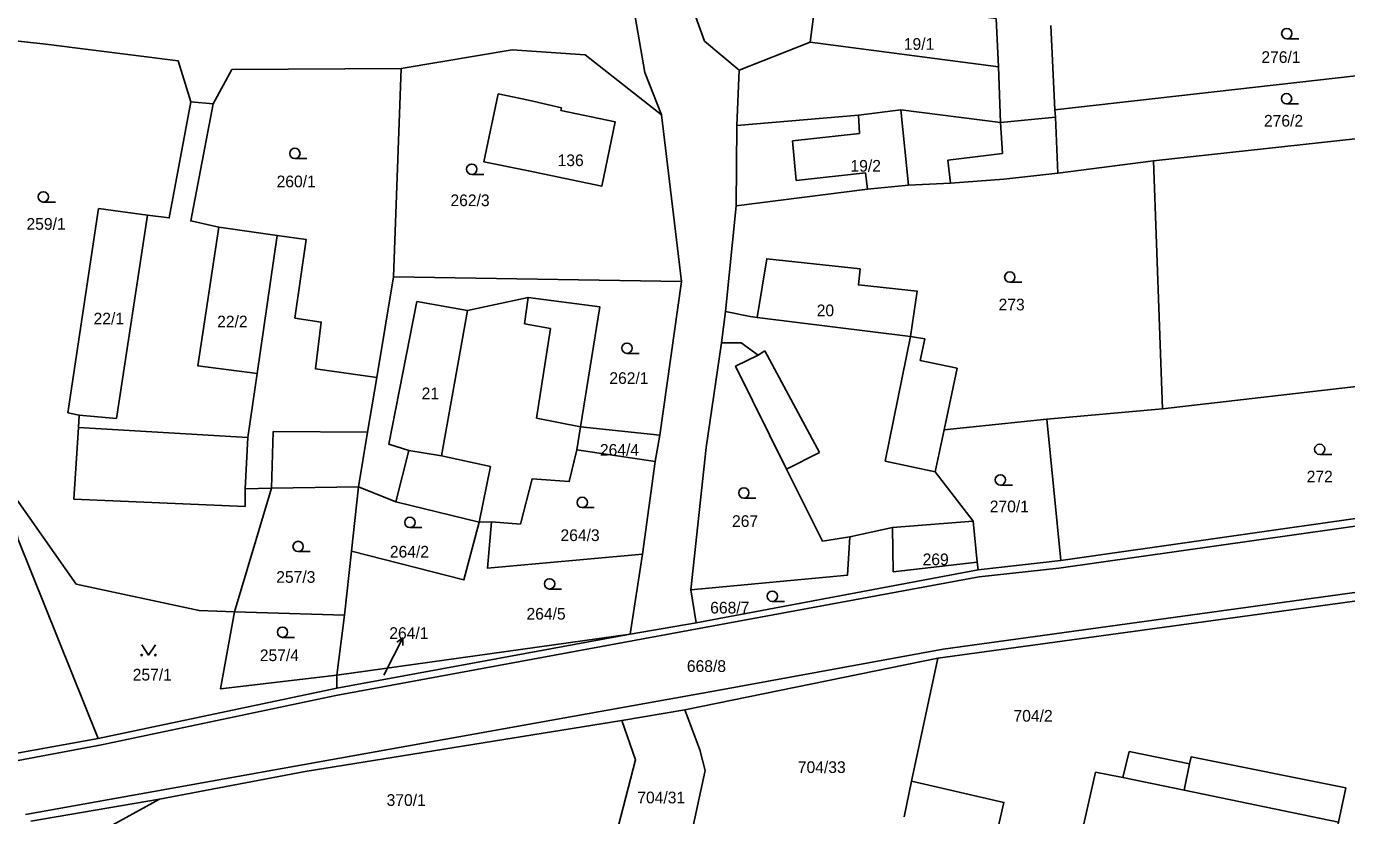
# Model space of a CAD drawing. Extents: x -747333 to -743907, y -1134120 to -1130051.
# Drawn here: x -746332 to -746140.1, y -1132327 to -1132212.3 of the extents above; entities that cross this region are included whole.
import ezdxf

# ---------------------------------------------------------------- set-up
doc = ezdxf.new("R2010")
doc.units = 0
for name, color, linetype in [('Hranice parcel', 7, 'Continuous'), ('Parcelní čísla', 7, 'Continuous'), ('Pop  PČ popisy', 7, 'Continuous'), ('Vnitřní kresba', 7, 'Continuous'), ('Značky kultur', 7, 'Continuous')]:
    doc.layers.add(name, color=color, linetype=linetype)

msp = doc.modelspace()

# ---------------------------------------------------------------- linework, layer by layer
at = {"layer": 'Hranice parcel'}
for p, q in [((-746182.52, -1132224.41), (-746183.12, -1132212.16)), ((-746182.52, -1132224.41), (-746109, -1132216.08)), ((-746278.68, -1132248.7), (-746277.54, -1132218.41)), ((-746228.44, -1132218.67), (-746228.78, -1132226.71)), ((-746304.89, -1132223.54), (-746308.1, -1132223.28)), ((-746236.8, -1132249.39), (-746239.72, -1132225.13)), ((-746182.46, -1132225.48), (-746182.52, -1132224.41)), ((-746182.13, -1132233.61), (-746182.46, -1132225.48)), ((-746108.49, -1132225.34), (-746168.2, -1132231.85)), ((-746228.78, -1132226.71), (-746228.86, -1132238.35)), ((-746168.2, -1132231.85), (-746182.13, -1132233.61)), ((-746168.2, -1132231.85), (-746166.89, -1132267.89)), ((-746228.86, -1132238.35), (-746230.4, -1132253.74)), ((-746281.1, -1132263.3), (-746278.68, -1132248.7)), ((-746236.8, -1132249.39), (-746278.68, -1132248.7)), ((-746239.94, -1132271.7), (-746236.8, -1132249.39)), ((-746230.4, -1132253.74), (-746231, -1132258.27)), ((-746166.89, -1132267.89), (-746107.13, -1132260.96)), ((-746166.89, -1132267.89), (-746183.71, -1132269.4)), ((-746183.71, -1132269.4), (-746198.64, -1132270.93)), ((-746181.66, -1132289.93), (-746183.71, -1132269.4)), ((-746252, -1132273.84), (-746251.48, -1132270.51)), ((-746251.48, -1132270.51), (-746239.94, -1132271.7)), ((-746240.62, -1132275.55), (-746239.94, -1132271.7)), ((-746240.62, -1132275.55), (-746252, -1132273.84)), ((-746242.47, -1132288.99), (-746240.62, -1132275.55)), ((-746296.38, -1132279.4), (-746301.77, -1132297.36)), ((-746300.23, -1132279.48), (-746296.38, -1132279.4)), ((-746296.38, -1132279.4), (-746283.73, -1132279.22)), ((-746284.76, -1132288.58), (-746283.73, -1132279.22)), ((-746283.73, -1132279.22), (-746278.34, -1132281.37)), ((-746181.66, -1132289.93), (-746104.68, -1132278.92)), ((-746278.34, -1132281.37), (-746266.19, -1132284.36)), ((-746266.19, -1132284.36), (-746264.4, -1132284.28)), ((-746212.36, -1132286.5), (-746206.12, -1132285.13)), ((-746206.12, -1132285.13), (-746194.4, -1132284.2)), ((-746193.82, -1132290.15), (-746194.4, -1132284.2)), ((-746285.78, -1132297.87), (-746284.76, -1132288.58)), ((-746242.47, -1132288.99), (-746244.25, -1132300.62)), ((-746234.67, -1132298.99), (-746193.71, -1132291.29)), ((-746193.82, -1132290.15), (-746193.71, -1132291.29)), ((-746193.71, -1132291.29), (-746181.66, -1132289.93)), ((-746235.45, -1132294.2), (-746234.67, -1132298.99)), ((-746129.73, -1132294.57), (-746199.56, -1132304.09)), ((-746301.77, -1132297.36), (-746285.78, -1132297.87)), ((-746286.89, -1132306.6), (-746285.78, -1132297.87)), ((-746244.25, -1132300.62), (-746234.67, -1132298.99)), ((-746244.25, -1132300.62), (-746286.89, -1132306.6)), ((-746286.89, -1132308.48), (-746244.25, -1132300.62)), ((-746199.56, -1132304.09), (-746236.32, -1132311.64)), ((-746199.56, -1132304.09), (-746203.36, -1132322.01)), ((-746286.89, -1132308.48), (-746286.89, -1132306.6)), ((-746321.59, -1132315.77), (-746286.89, -1132308.48)), ((-746236.32, -1132311.64), (-746245.46, -1132313.16)), ((-746234.16, -1132317.42), (-746236.32, -1132311.64)), ((-746245.46, -1132313.16), (-746243.49, -1132318.9)), ((-746338.75, -1132318.87), (-746321.59, -1132315.77)), ((-746243.49, -1132318.9), (-746246.67, -1132331.25)), ((-746204.45, -1132327.15), (-746203.36, -1132322.01)), ((-746312.67, -1132324.59), (-746331.35, -1132327.82))]:
    msp.add_line(p, q, dxfattribs=at)
for points in [[(-746239.72, -1132225.13), (-746242.13, -1132218.98), (-746247.56, -1132187.7), (-746250.26, -1132174.19)], [(-746239.96, -1132195.24), (-746238.89, -1132199.39), (-746233.44, -1132214.44), (-746228.44, -1132218.67)], [(-746191.06, -1132211.13), (-746211.76, -1132208.57), (-746211.51, -1132206.18), (-746216.94, -1132205.61), (-746218.08, -1132214.58), (-746228.44, -1132218.67)], [(-746308.1, -1132223.28), (-746309.97, -1132217.3), (-746329.17, -1132214.87), (-746349.14, -1132212.69)], [(-746239.72, -1132225.13), (-746250.79, -1132216.43), (-746261.41, -1132215.72), (-746277.54, -1132218.41)], [(-746277.54, -1132218.41), (-746302.15, -1132218.58), (-746304.89, -1132223.54)], [(-746263.45, -1132222.08), (-746265.54, -1132231.97), (-746259.04, -1132233.31), (-746248.37, -1132235.5), (-746246.42, -1132226.19), (-746254.34, -1132224.51), (-746254.26, -1132224.12)], [(-746254.26, -1132224.12), (-746259.05, -1132223), (-746263.45, -1132222.08)], [(-746308.1, -1132223.28), (-746311.26, -1132240.14), (-746314.42, -1132239.71), (-746321.52, -1132238.77), (-746325.97, -1132268.44), (-746324.34, -1132268.79), (-746324.45, -1132270.59), (-746325.11, -1132281.02), (-746300.23, -1132282.05), (-746300.23, -1132279.48)], [(-746304.05, -1132241.46), (-746308.13, -1132240.56), (-746304.89, -1132223.54)], [(-746228.78, -1132226.71), (-746211.08, -1132225.19), (-746204.95, -1132224.4), (-746190.42, -1132226.25), (-746182.46, -1132225.48)], [(-746228.86, -1132238.35), (-746209.78, -1132235.95), (-746203.81, -1132235.37), (-746197.7, -1132235.09), (-746189.94, -1132234.52), (-746182.13, -1132233.61)], [(-746300.23, -1132279.48), (-746299.84, -1132272.04), (-746298.48, -1132262.72), (-746307.11, -1132261.61), (-746304.05, -1132241.46)], [(-746281.1, -1132263.3), (-746290.01, -1132262.04), (-746289.16, -1132255.28), (-746293, -1132254.68), (-746291.36, -1132243.25), (-746295.57, -1132242.7), (-746304.05, -1132241.46)], [(-746198.64, -1132270.93), (-746196.75, -1132261.98), (-746202.11, -1132260.85), (-746201.45, -1132257.7), (-746203.54, -1132257.38), (-746202.53, -1132250.79), (-746211.09, -1132249.87), (-746210.84, -1132247.53), (-746224.42, -1132246.06), (-746225.81, -1132254.58), (-746226.81, -1132254.45), (-746230.4, -1132253.74)], [(-746251.48, -1132270.51), (-746248.66, -1132253.06), (-746259.09, -1132251.69), (-746267.9, -1132253.57), (-746275.26, -1132252.29), (-746279.36, -1132272.99), (-746276.45, -1132273.93), (-746278.34, -1132281.37)], [(-746231, -1132258.27), (-746233.22, -1132273.5), (-746235.45, -1132294.2)], [(-746231, -1132258.27), (-746228.13, -1132258.26), (-746225.64, -1132260.1), (-746228.95, -1132261.69), (-746221.54, -1132276.63), (-746216.3, -1132287.1), (-746212.36, -1132286.5)], [(-746283.73, -1132279.22), (-746282.42, -1132271.26), (-746281.1, -1132263.3)], [(-746194.4, -1132284.2), (-746199.93, -1132277.03), (-746198.64, -1132270.93)], [(-746264.4, -1132284.28), (-746260.21, -1132284.62), (-746258.5, -1132278.03), (-746253.11, -1132278.46), (-746252, -1132273.84)], [(-746301.77, -1132297.36), (-746306.9, -1132297.19), (-746324.77, -1132293.34), (-746334.69, -1132279.22)], [(-746334.69, -1132279.22), (-746333.21, -1132286.86), (-746321.59, -1132315.77)], [(-746284.76, -1132288.58), (-746268.42, -1132292.74), (-746266.19, -1132284.36)], [(-746264.4, -1132284.28), (-746265, -1132291.03), (-746242.47, -1132288.99)], [(-746206.12, -1132285.13), (-746206.03, -1132291.55), (-746193.82, -1132290.15)], [(-746235.45, -1132294.2), (-746212.7, -1132292.06), (-746212.36, -1132286.5)], [(-746286.89, -1132306.6), (-746303.82, -1132308.56), (-746301.77, -1132297.36)], [(-746245.46, -1132313.16), (-746291.48, -1132320.59), (-746312.67, -1132324.59)], [(-746235.51, -1132330.26), (-746233.35, -1132320.43), (-746234.16, -1132317.42)], [(-746176.65, -1132320.68), (-746179.36, -1132332.68), (-746143.97, -1132340.17), (-746141.34, -1132327.96), (-746140.26, -1132322.97), (-746162.74, -1132318.47), (-746162.95, -1132319.47), (-746171.73, -1132317.69), (-746172.66, -1132321.47), (-746176.65, -1132320.68)], [(-746203.36, -1132322.01), (-746189.95, -1132325.07), (-746192.75, -1132337.33)], [(-746312.67, -1132324.59), (-746321.38, -1132329.41), (-746329.35, -1132338.1)]]:
    msp.add_lwpolyline(points, dxfattribs=at)
at = {"layer": 'Pop  PČ popisy'}
for p, q in [((-746278.65, -1132303.81), (-746277.288, -1132301.136)), ((-746277.288, -1132301.136), (-746278.188, -1132301.801)), ((-746277.288, -1132301.136), (-746277.296, -1132302.256)), ((-746280.07, -1132306.57), (-746278.65, -1132303.81))]:
    msp.add_line(p, q, dxfattribs=at)
at = {"layer": 'Vnitřní kresba'}
for p, q in [((-746191.06, -1132211.13), (-746190.75, -1132218.16)), ((-746218.08, -1132214.58), (-746190.75, -1132218.16)), ((-746190.75, -1132218.16), (-746190.42, -1132226.25)), ((-746211.08, -1132225.19), (-746210.92, -1132227.88)), ((-746203.81, -1132235.37), (-746204.95, -1132224.4)), ((-746210.92, -1132227.88), (-746220.66, -1132228.95)), ((-746190.42, -1132226.25), (-746190.14, -1132230.77)), ((-746220.66, -1132228.95), (-746220.16, -1132234.7)), ((-746190.14, -1132230.77), (-746198.1, -1132231.73)), ((-746198.1, -1132231.73), (-746197.7, -1132235.09)), ((-746220.16, -1132234.7), (-746210.06, -1132233.59)), ((-746210.06, -1132233.59), (-746209.78, -1132235.95)), ((-746318.91, -1132269.3), (-746314.42, -1132239.71)), ((-746298.48, -1132262.72), (-746295.57, -1132242.7)), ((-746259.09, -1132251.69), (-746259.61, -1132255.54)), ((-746267.9, -1132253.57), (-746271.66, -1132274.7)), ((-746225.81, -1132254.58), (-746203.54, -1132257.38)), ((-746259.61, -1132255.54), (-746255.84, -1132256.22)), ((-746255.84, -1132256.22), (-746257.9, -1132269.22)), ((-746203.54, -1132257.38), (-746207.21, -1132275.49)), ((-746225.64, -1132260.1), (-746224.67, -1132259.47)), ((-746224.67, -1132259.47), (-746216.77, -1132274.2)), ((-746324.34, -1132268.79), (-746318.91, -1132269.3)), ((-746257.9, -1132269.22), (-746251.48, -1132270.51)), ((-746299.84, -1132272.04), (-746324.45, -1132270.59)), ((-746296.38, -1132279.4), (-746296.17, -1132271.19)), ((-746296.17, -1132271.19), (-746282.42, -1132271.26)), ((-746271.66, -1132274.7), (-746276.45, -1132273.93)), ((-746221.54, -1132276.63), (-746216.77, -1132274.2)), ((-746271.66, -1132274.7), (-746264.57, -1132276.24)), ((-746207.21, -1132275.49), (-746199.93, -1132277.03)), ((-746264.57, -1132276.24), (-746266.19, -1132284.36)), ((-746100.31, -1132279.44), (-746181.96, -1132291.03)), ((-746181.96, -1132291.03), (-746193.54, -1132292.28)), ((-746193.54, -1132292.28), (-746287.05, -1132309.52)), ((-746198.77, -1132302.82), (-746129.47, -1132293.24)), ((-746231.85, -1132308.88), (-746198.77, -1132302.82)), ((-746332.14, -1132326.83), (-746231.85, -1132308.88)), ((-746287.05, -1132309.52), (-746321.12, -1132316.7)), ((-746321.12, -1132316.7), (-746338.63, -1132320.01)), ((-746162.95, -1132319.47), (-746163.76, -1132323.31)), ((-746172.66, -1132321.47), (-746163.76, -1132323.31)), ((-746163.76, -1132323.31), (-746141.34, -1132327.96))]:
    msp.add_line(p, q, dxfattribs=at)
at = {"layer": 'Značky kultur'}
for p, q in [((-746148.833, -1132214.1), (-746147.083, -1132214.1)), ((-746148.873, -1132223.55), (-746147.123, -1132223.55)), ((-746292.993, -1132231.5), (-746291.243, -1132231.5)), ((-746267.293, -1132233.81), (-746265.543, -1132233.81)), ((-746329.553, -1132237.82), (-746327.803, -1132237.82)), ((-746189.093, -1132249.47), (-746187.343, -1132249.47)), ((-746244.723, -1132259.81), (-746242.973, -1132259.81)), ((-746144.053, -1132274.51), (-746142.303, -1132274.51)), ((-746190.463, -1132278.96), (-746188.713, -1132278.96)), ((-746227.743, -1132280.85), (-746225.993, -1132280.85)), ((-746251.223, -1132282.22), (-746249.473, -1132282.22)), ((-746276.273, -1132285.13), (-746274.523, -1132285.13)), ((-746292.523, -1132288.63), (-746290.773, -1132288.63)), ((-746255.973, -1132294.06), (-746254.223, -1132294.06)), ((-746223.603, -1132295.87), (-746221.853, -1132295.87)), ((-746294.793, -1132301.09), (-746293.043, -1132301.09))]:
    msp.add_line(p, q, dxfattribs=at)
msp.add_lwpolyline([(-746315.26, -1132302.159), (-746314.26, -1132303.66), (-746313.26, -1132302.159)], dxfattribs=at)
for centre, radius in [((-746148.833, -1132213.35), 0.75), ((-746148.873, -1132222.8), 0.75), ((-746292.993, -1132230.75), 0.75), ((-746267.293, -1132233.06), 0.75), ((-746329.553, -1132237.07), 0.75), ((-746189.093, -1132248.72), 0.75), ((-746244.723, -1132259.06), 0.75), ((-746144.053, -1132273.76), 0.75), ((-746190.463, -1132278.21), 0.75), ((-746227.743, -1132280.1), 0.75), ((-746251.223, -1132281.47), 0.75), ((-746276.273, -1132284.38), 0.75), ((-746292.523, -1132287.88), 0.75), ((-746255.973, -1132293.31), 0.75), ((-746223.603, -1132295.12), 0.75), ((-746294.793, -1132300.34), 0.75), ((-746315.26, -1132303.659), 0.1), ((-746313.26, -1132303.659), 0.1)]:
    msp.add_circle(centre, radius, dxfattribs=at)

# ---------------------------------------------------------------- texts
at = {"layer": 'Parcelní čísla'}
for s, p in [('19/1', (-746204.49, -1132215.7)), ('276/1', (-746152.523, -1132217.61)), ('276/2', (-746152.153, -1132226.86)), ('136', (-746254.81, -1132232.6)), ('19/2', (-746212.24, -1132233.41)), ('260/1', (-746295.65, -1132235.68)), ('262/3', (-746270.38, -1132238.42)), ('259/1', (-746332, -1132241.85)), ('20', (-746217.15, -1132254.42)), ('273', (-746190.72, -1132253.57)), ('22/1', (-746322.25, -1132255.61)), ('22/2', (-746304.29, -1132256.04)), ('262/1', (-746247.29, -1132264.26)), ('21', (-746274.57, -1132266.48)), ('264/4', (-746248.66, -1132274.69)), ('272', (-746145.94, -1132278.57)), ('270/1', (-746192, -1132282.91)), ('267', (-746229.46, -1132285.04)), ('264/3', (-746254.39, -1132287.09)), ('264/2', (-746279.19, -1132289.49)), ('269', (-746201.76, -1132290.6)), ('257/3', (-746295.7, -1132293.16)), ('264/5', (-746259.33, -1132298.51)), ('668/7', (-746232.63, -1132297.62)), ('264/1', (-746279.273, -1132301.32)), ('257/4', (-746298.09, -1132304.54)), ('668/8', (-746236.023, -1132306.11)), ('257/1', (-746316.56, -1132307.36)), ('704/2', (-746188.55, -1132313.34)), ('704/33', (-746219.895, -1132320.8)), ('370/1', (-746279.66, -1132325.58)), ('704/31', (-746243.225, -1132325.21))]:
    msp.add_text(s, height=1.7, dxfattribs=at).set_placement(p)

doc.saveas('drawing.dxf')
